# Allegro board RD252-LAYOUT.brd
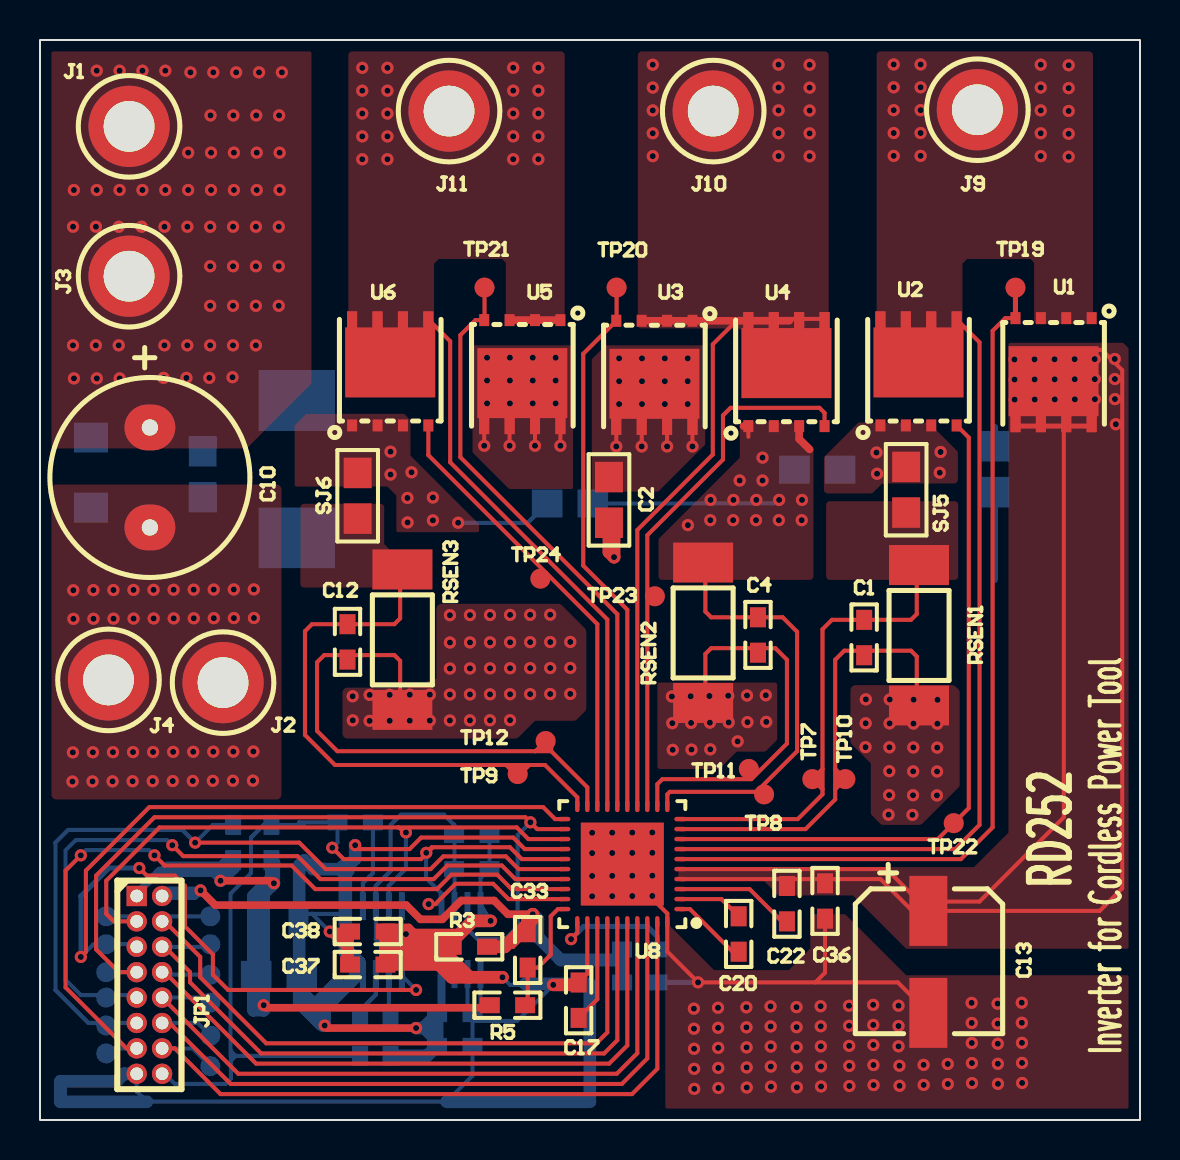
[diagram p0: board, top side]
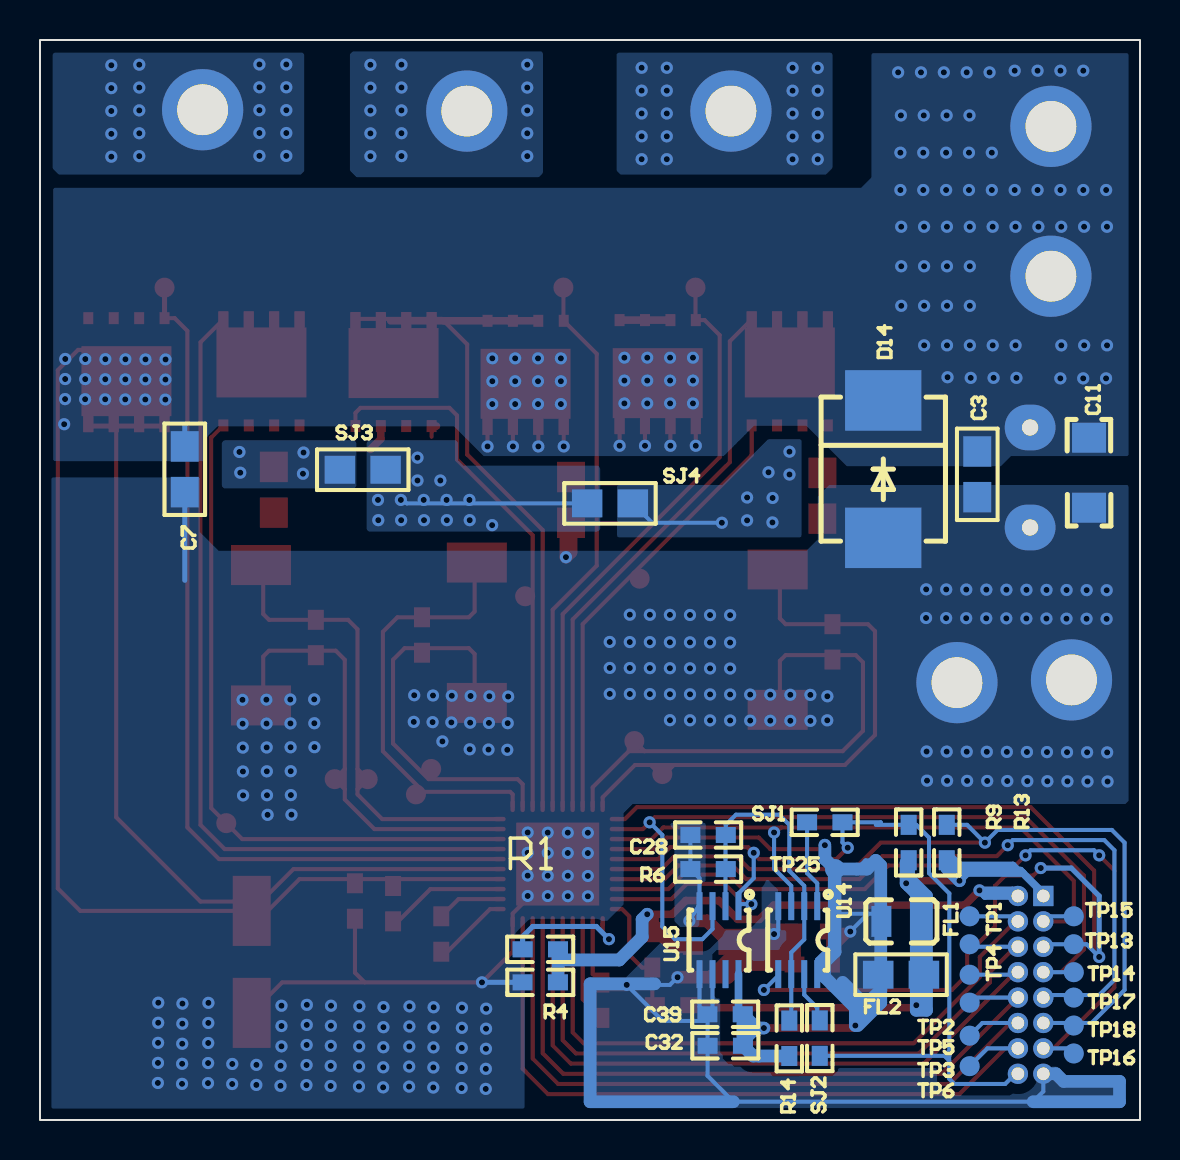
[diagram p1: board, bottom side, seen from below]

Outline 55 x 54 mm; copper layers: TOP, BOTTOM. Coordinates in mm from the lower left corner of the outline.
Outline path: rectangle 0,0 55,54

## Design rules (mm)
constraint set DEFAULT: 

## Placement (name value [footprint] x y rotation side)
C1  -  [0603]  41.21 25.01 270 top
C2  -  [0805]  28.45 32.15 270 top
C3  -  [0805]  8.14 33.43 270 bottom
C4  -  [0603]  35.9 25.14 270 top
C7  -  [0805]  47.76 33.68 270 bottom
C10  -  [CAP_10MM]  5.49 34.63 180 top
C11  -  [0603#3]  2.55 34.12 90 bottom
C12  -  [0603]  15.38 24.79 270 top
C13  -  [CASE_B2]  44.42 10.46 270 top
C17  -  [0603]  26.93 5.11 90 top
C20  -  [0603]  34.93 10.19 270 top
C22  -  [0603]  37.35 9.93 90 top
C28  -  [0603]  20.71 14.25 0 bottom
C32  -  [0603]  19.85 3.71 0 bottom
C33  -  [0603]  24.38 7.62 90 top
C36  -  [0603]  39.25 11.84 270 top
C37  -  [0603]  15.5 7.77 0 top
C38  -  [0603]  15.5 9.42 0 top
C39  -  [0603]  19.86 5.29 0 bottom
D14  -  [DSMC]  12.84 29.11 270 bottom
FL1  -  [L0805]  10.93 9.93 0 bottom
FL2  -  [L0805#2]  13.09 7.26 180 bottom
J1  -  [TP_SM]  4.45 49.68 180 top
J2  -  [TP_SM]  9.15 21.87 180 top
J3  -  [TP_SM]  4.45 42.19 0 top
J4  -  [TP_SM]  3.42 22 0 top
J9  -  [TP_SM]  46.87 50.51 0 top
J10  -  [TP_SM]  33.66 50.45 0 top
J11  -  [TP_SM]  20.45 50.45 0 top
JP1  -  [IDC16_1_27MM]  4.83 11.2 270 top
R1  -  [0603]  30.87 8.53 180 bottom
R3  -  [0603]  20.58 8.66 0 top
R4  -  [0603]  29.1 6.88 0 bottom
R5  -  [0603]  22.49 5.74 0 top
R6  -  [0603]  20.71 12.55 0 bottom
R9  -  [0603]  11.57 14.76 270 bottom
R13  -  [0603]  9.66 14.76 270 bottom
R14  -  [0603]  17.54 3.2 90 bottom
RSEN1  -  [2512]  43.95 20.73 270 top
RSEN2  -  [2512]  33.16 20.85 270 top
RSEN3  -  [2512]  18.12 20.51 270 top
SJ1  -  [0603]  16.65 14.88 180 bottom
SJ2  -  [0603]  16.01 4.98 270 bottom
SJ3  -  [0603#2]  40.01 32.51 180 bottom
SJ4  -  [0603#2]  27.64 30.83 180 bottom
SJ5  -  [0603#2]  43.31 30.37 90 top
SJ6  -  [0603#2]  15.88 30.07 90 top
TP1  -  [TP2]  8.52 10.19 0 bottom
TP2  -  [TP2]  8.52 7.26 0 bottom
TP3  -  [TP2]  8.52 4.22 0 bottom
TP4  -  [TP2]  8.52 8.79 270 bottom
TP5  -  [TP2]  8.52 5.87 270 bottom
TP6  -  [TP2]  8.52 2.69 270 bottom
TP7  -  [TP2]  38.62 17.04 0 top
TP8  -  [TP2]  36.2 16.28 180 top
TP9  -  [TP2]  23.89 17.3 180 top
TP10  -  [TP2]  40.27 17.04 180 top
TP11  -  [TP2]  35.44 17.55 180 top
TP12  -  [TP2]  25.28 18.95 270 top
TP13  -  [TP2]  3.31 8.79 90 bottom
TP14  -  [TP2]  3.31 7.39 90 bottom
TP15  -  [TP2]  3.31 10.19 90 bottom
TP16  -  [TP2]  3.31 3.33 90 bottom
TP17  -  [TP2]  3.31 6.12 90 bottom
TP18  -  [TP2]  3.31 4.72 90 bottom
TP19  -  [TP2]  48.77 41.62 0 top
TP20  -  [TP2]  28.83 41.62 180 top
TP21  -  [TP2]  22.23 41.62 180 top
TP22  -  [TP2]  45.69 14.84 180 top
TP23  -  [TP2]  30.74 26.19 180 top
TP24  -  [TP2]  25.02 27.07 180 top
TP25  -  [TP2]  15.25 12.55 90 bottom
U1  -  [SOP_8T]  52.58 40.09 0 top
U2  -  [SOP_8T]  42.02 34.73 180 top
U3  -  [SOP_8T]  32.62 39.96 0 top
U4  -  [SOP_8T]  35.42 34.7 180 top
U5  -  [SOP_8T]  26.02 40 0 top
U6  -  [SOP_8T]  15.61 34.73 180 top
U8  -  [WQFN_40]  32.02 10.55 180 top
U14  -  [SSOP_8]  16.14 10.69 0 bottom
U15  -  [SSOP_8]  20.07 10.69 0 bottom

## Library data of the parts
C1 C4 C12 = 0.001uF
C2 C3 C7 = 10uF
C10 = 220uF_60V
C11 C32 C36 = 0.1uF: alternate symbols: (1206)
C13 = 20uF_60V
C17 C28 C37 C38 = 1uF
C20 = 47nF/16V
C22 = 1uF/16V
C33 = 100nF
C39 = 4.7uF
D14 = SMCJ22A
FL1 FL2 = BLM21PG221SN1D: alternate symbols: (0805)
J1 J3 = INV
J2 J4 = PGND
J9 = MOTOR_U
J10 = MOTOR_V
J11 = MOTOR_W
JP1 = CONN_16PINJ
R1 = O_OHM
R3 R4 = 0E
R5 R9 R13 = 10K
R6 = 1.5k/0.1%
R14 = 100k/0.1%
RSEN1-RSEN3 = 5mOhm_5W
SJ1-SJ6 = SJ: alternate symbols: (0805)
TP1-TP25 = TPB1_27
U1-U6 = TPH1R204PB: alternate symbols: (SOP_8T_1)
U8 = DRV8323S
U14 U15 = TC75W58FK

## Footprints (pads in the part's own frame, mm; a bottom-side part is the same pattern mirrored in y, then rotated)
0603
  rect 1x0.8 smd: 1(0,0) 2(1.77,0)
0603#2
  rect 1.524x1.397 smd: 1(0,0) 2(2.286,0)
0603#3
  rect 1.5x1.7 smd: 1(0,0) 2(-3.5,0)
0805
  rect 1.524x1.397 smd: 1(0,0) 2(2.286,0)
2512
  rect 2x3 smd: 1(0,0) 2(-7.021,0)
CAP_10MM
  oval 2.54x2.286 hole 0.813: 1(0,0) 2(0,5)
CASE_B2
  rect 3.5x1.9 smd: 1(0,0) 2(5.1,0)
DSMC
  rect 3.03x3.82 smd: A(0,0) C(-6.87,0)
IDC16_1_27MM
  rect 1.016x1.016 hole 0.635: 1(0,0)
  round 1.016 hole 0.635: 2(0,1.27) 3(1.27,0) 4(1.27,1.27) 5(2.54,0) 6(2.54,1.27) 7(3.81,0) 8(3.81,1.27) 9(5.08,0) 10(5.08,1.27) 11(6.35,0) 12(6.35,1.27) 13(7.62,0) 14(7.62,1.27) 15(8.89,0) 16(8.89,1.27)
L0805
  rect 1x1.55 smd: 1(0,0) 2(2,0)
L0805#2
  rect 1.524x1.397 smd: 1(0,0) 2(2.286,0)
SOP_8T
  rect 0.5x0.6 smd: 1(0,0) 2(-1.27,0) 3(-2.54,0) 4(-3.81,0)
  rect 0.5x0.8 smd: 5(-3.81,-5.3) 6(-2.54,-5.3) 7(-1.27,-5.3) 8(0,-5.3)
SSOP_8
  rect 0.3x1.4 smd: 1(0,0) 2(0.65,0) 3(1.3,0) 4(1.95,0) 5(1.95,3.4) 6(1.3,3.4) 7(0.65,3.4) 8(0,3.4)
TP2
  round 1 smd: 1(0,0)
TP_SM
  round 4.064 hole 2.54: 1(0,0)
WQFN_40
  oval 0.6x0.22 smd: 1(0,0) 2(0,-0.5) 3(0,-1) 4(0,-1.5) 5(0,-2) 6(0,-2.5) 7(0,-3) 8(0,-3.5) 9(0,-4) 10(0,-4.5) 21(5.8,-4.5) 22(5.8,-4) 23(5.8,-3.5) 24(5.8,-3) 25(5.8,-2.5) 26(5.8,-2) 27(5.8,-1.5) 28(5.8,-1) 29(5.8,-0.5) 30(5.8,0)
  oval 0.22x0.6 smd: 11(0.65,-5.15) 12(1.15,-5.15) 13(1.65,-5.15) 14(2.15,-5.15) 15(2.65,-5.15) 16(3.15,-5.15) 17(3.65,-5.15) 18(4.15,-5.15) 19(4.65,-5.15) 20(5.15,-5.15) 31(5.15,0.65) 32(4.65,0.65) 33(4.15,0.65) 34(3.65,0.65) 35(3.15,0.65) 36(2.65,0.65) 37(2.15,0.65) 38(1.65,0.65) 39(1.15,0.65) 40(0.65,0.65)
  rect 4.15x4.15 smd: 41(2.9,-2.25)

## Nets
+5V: FL1.1 FL2.2 JP1.1 R5.1 R9.2 R13.2
+5V_A: C32.1 C37.1 C38.1 C39.1 FL1.2 FL2.1 R14.1 TP25.1 U8.24 U14.8 U15.8
AGND: C17.2 C28.2 C32.2 C37.2 C38.2 C39.2 JP1.15 R3.1 R6.2 U8.32 U14.4 U15.4 U15.5 U15.6
GND: C33.2 JP1.2 R1.2 R3.2 R4.1
PGND: C1.2 C2.2 C3.2 C4.2 C7.2 C10.2 C11.2 C12.2 C13.2 C36.2 D14.A J2.1 J4.1 R4.2 RSEN1.1 RSEN2.1 RSEN3.1 TP10.1 TP11.1 TP12.1 U8.9 U8.12 U8.19 U8.40 U8.41
V0: JP1.8 TP2.1 U8.36
AINB10: JP1.3 TP15.1 U8.23 U14.3
AINB11: JP1.7 TP14.1 U8.22 U15.3
AINB12: JP1.5 TP13.1 U8.21 U14.5
EMG: JP1.16 R9.1 SJ1.2 SJ2.2 U8.25 U8.29 U15.1
GHA: TP19.1 U1.4 U8.6
GHB: TP20.1 U3.4 U8.15
GHC: TP21.1 U5.4 U8.16
GLA: TP22.1 U2.4 U8.8
GLB: TP23.1 U4.4 U8.13
GLC: TP24.1 U6.4 U8.18
NETC22_1: C22.1 U8.3
NETR1_1: R1.1 U8.31
NETR5_2: C33.1 R5.2 U8.30
NETR14_2: C28.1 R6.1 R14.2 U14.2 U14.6 U15.2
NETSJ4_2: SJ4.2 SJ6.2 U6.1 U6.2 U6.3
NETU2_1: SJ3.1 SJ5.2 U2.1 U2.2 U2.3
NETU8_1: C20.2 U8.1
NETU8_2: C20.1 U8.2
NETU8_33: C17.1 U8.33
NETU14_1: SJ1.1 U14.1
NETU14_7: SJ2.1 U14.7
SCLK: JP1.13 TP16.1 U8.28
SDI: JP1.9 TP17.1 U8.27
SDO: JP1.11 R13.1 TP18.1 U8.26
SHA: J9.1 U1.1 U1.2 U1.3 U2.5 U2.6 U2.7 U2.8 U8.7
SHB: J10.1 U3.1 U3.2 U3.3 U4.5 U4.6 U4.7 U4.8 U8.14
SHC: J11.1 U5.1 U5.2 U5.3 U6.5 U6.6 U6.7 U6.8 U8.17
SNA: C1.1 RSEN1.2 SJ5.1 TP7.1 U8.10
SNB: C4.1 RSEN2.2 SJ3.2 SJ4.1 TP8.1 U4.1 U4.2 U4.3 U8.11
SNC: C12.1 RSEN3.2 SJ6.1 TP9.1 U8.20
U0: JP1.4 TP1.1 U8.34
VM: C2.1 C3.1 C7.1 C10.1 C11.1 C13.1 C22.2 C36.1 D14.C J1.1 J3.1 U1.5 U1.6 U1.7 U1.8 U3.5 U3.6 U3.7 U3.8 U5.5 U5.6 U5.7 U5.8 U8.4 U8.5
W0: JP1.12 TP3.1 U8.38
X0: JP1.6 TP4.1 U8.35
Y0: JP1.10 TP5.1 U8.37
Z0: JP1.14 TP6.1 U8.39

Pads without a net: U15 7

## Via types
v1: diameter 0.61, hole 0.305, TOP to BOTTOM, 418 vias

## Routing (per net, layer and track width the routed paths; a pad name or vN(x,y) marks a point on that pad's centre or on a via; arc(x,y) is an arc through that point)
+5V: length 51.1
  TOP w0.381: v1(11.19,5.74) 11.31,5.61 22.36,5.61 R5.1 ; v1(11.69,11.84) 11.57,11.96 v1(9.03,11.96)
  BOTTOM w0.203: v1(11.19,5.74) 10.93,5.99 10.93,6.88 ; FL2.2 10.8,10.06
  BOTTOM w0.381: 9.03,12.35 9.14,12.47 ; 9.03,12.35 5.86,12.35 ; 9.03,12.35 v1(9.03,11.96) 8.52,12.47 ; 9.14,12.47 8.52,12.47 ; 9.14,12.47 R13.2 ; JP1.1 4.83,11.33 5.86,12.35 ; 5.86,12.35 5.98,12.47 6.11,12.47 ; 11.19,11.33 10.8,10.95 10.8,10.06 ; 6.11,12.47 6.36,12.72 9.03,12.72 9.41,13.11 ; 6.11,12.47 8.52,12.47 ; 11.57,11.71 11.57,12.09
  BOTTOM w0.635: v1(9.03,11.96) 9.66,12.6 R13.2 ; R9.2 11.69,12.86 v1(11.69,11.84) 11.19,11.33 v1(11.19,5.74) 11.19,5.49 10.68,5.49 10.68,11.2 11.57,12.09 R9.2
+5V_A: length 70.5
  TOP w0.203: U8.24 24.24,13.55 23.66,14.12 19.06,14.12 18.48,13.55 15.95,13.55 v1(15.76,13.74) ; C38.1 15.76,9.42
  TOP w0.381: 14.99,9.42 C38.1 C37.1 ; 14.99,9.42 v1(14.49,9.42) 15.38,8.53 ; 14.99,9.42 15.25,9.17 15.25,7.77 ; v1(14.23,4.72) 14.36,4.6 v1(18.8,4.6)
  BOTTOM w0.203: 13.6,10.31 v1(14.49,9.42) ; 13.6,10.31 12.96,10.31 ; 13.6,10.31 15.5,10.31 ; 13.22,12.98 13.72,12.98 14.16,12.55 ; 19.06,3.2 19.57,3.71 19.85,3.71 19.86,3.72 ; 15.5,10.31 15.5,8.66 16.14,8.03 16.14,7.52 15.77,7.15 ; 15.5,10.31 15.5,12.47 ; 15.15,12.37 15.23,12.55 ; 19.22,4.6 19.86,4.6 ; C39.1 20.07,5.5
  BOTTOM w0.381: 19.34,3.2 19.86,3.72 C39.1 19.17,4.6 ; 19.85,5.11 20.07,5.33 U15.8
  BOTTOM w0.635: 14.23,5.23 14.23,5.61 15.77,7.15 15.77,7.88 15.25,8.41 TP25.1 ; 14.23,5.23 12.96,6.5 ; 14.23,5.23 v1(14.23,4.72) ; v1(15.76,13.74) 15.76,13.05 TP25.1 ; 19.85,3.96 19.22,4.6 19.17,4.6 ; 19.85,3.96 C32.1 19.34,3.2 R14.1 ; 19.85,3.96 19.85,5.28 19.17,4.6 ; 19.17,4.6 v1(18.8,4.6) ; 12.96,6.5 12.96,12.72 13.22,12.98 13.65,12.55 TP25.1 ; 12.96,6.5 12.96,5.87 14.11,4.72 ; 13.98,5.99 14.87,6.88
AGND: length 100.5
  TOP w0.203: U8.32 27.37,7.31 C17.2 ; C38.2 18.17,9.42 v1(18.3,9.3)
  TOP w0.381: 18.69,9.37 20.95,9.37 ; 18.69,9.37 18.44,9.63 17.14,9.63 ; 18.69,9.37 18.95,9.12 19.81,9.12
  TOP w0.635: 20.8,9.12 21.64,9.96 v1(22.53,9.96) ; 20.8,9.12 20.35,8.66 ; 20.8,9.12 19.81,9.12 ; v1(25.66,6.76) 26.81,6.76 ; 17.27,8.26 20.07,8.26 20.45,7.87 ; 17.27,8.26 C37.2 ; 17.27,8.26 C38.2 17.58,9.12 18.95,9.12 ; 17.28,7.78 19.94,7.78 20.58,7.14 21.47,7.14 ; 20.35,8.66 R3.1 ; 20.35,8.66 17.3,8.66 17.65,9.02 20.19,9.02 ; 20.58,8.03 21.47,7.14 ; 21.47,7.14 v1(23.12,7.14)
  BOTTOM w0.203: U15.6 21.38,5.61 ; 21.38,5.61 21.62,5.37 21.62,5.28 ; 21.38,5.61 21.38,5.2 21.62,4.95 ; 21.62,5.28 22.02,5.68 U15.5 ; 21.62,5.28 21.62,4.95 ; v1(18.3,9.3) 18.09,9.51 U14.4 ; v1(22.53,9.96) 22.06,10.72 22.02,10.78 22.02,12.09 R6.2 C28.2 ; 21.62,4.95 23.86,4.95 v1(25.66,6.76) 23.5,6.76 v1(23.12,7.14) ; 21.62,4.95 C32.2 21.62,2.21 20.33,0.91 5.34,0.91 4.83,1.42 JP1.15
  BOTTOM w0.635: 24.26,6.81 27.49,6.81 27.49,0.91 20.33,0.91 ; 5.34,0.91 1.02,0.91 1.02,1.93 3.82,1.93 4.2,2.31 JP1.15
GND: length 35.6
  TOP w0.203: C33.2 23.66,8.66 23.24,8.66
  TOP w0.381: v1(24.64,10.29) 23.39,10.29 22.71,10.97 21.06,10.97 20.12,10.03 19.02,10.03 18.31,10.74 8.76,10.74 v1(8.03,11.48)
  TOP w0.635: R3.2 23.24,8.66 23.97,9.39 ; 23.97,9.39 C33.2 24.38,10.03 v1(24.64,10.29) 24.64,10.06 23.97,9.39
  BOTTOM w0.381: 6.38,11.48 v1(8.03,11.48) 7.75,11.2 JP1.2 6.38,11.48
  BOTTOM w0.635: 29.1,6.89 29.1,8.26 ; 29.1,8.26 28.85,8 26.04,8 24.89,9.14 24.89,10.03 v1(24.64,10.29) ; 29.1,8.26 R1.2
PGND: length 101.8
  TOP w0.203: 35.67,23.59 36.77,23.59 37.35,23.01 37.35,18.82 35.57,17.04 31.12,17.04 30.87,16.79 U8.12 ; 35.67,23.59 C4.2 ; 35.67,23.59 33.56,23.59 33.27,23.3 33.27,20.72 ; 39.76,16.54 TP10.1 39.76,17.55 ; 39.76,16.54 39.76,16.03 38.28,14.55 U8.9 ; 39.76,16.54 39.76,17.55 ; 25.56,18.44 25.56,18.67 TP12.1 24.77,18.44 ; 25.56,18.44 27.37,16.63 U8.19 ; 25.56,18.44 24.77,18.44 ; C36.2 39.25,7.37 38.77,6.88 ; 15.15,23.25 17.72,23.25 18.01,22.96 18.01,21.02 ; 15.15,23.25 C12.2 ; 15.15,23.25 14.21,23.25 13.85,22.89 13.85,19.46 14.87,18.44 24.77,18.44 ; 40.98,23.46 43.55,23.46 43.84,23.18 43.84,21.24 ; 40.98,23.46 40.21,23.46 39.76,23.01 39.76,17.55 ; 40.98,23.46 C1.2 ; 38.77,6.88 v1(32.9,6.88) 31.37,8.42 31.37,10.32 30.74,10.95 ; 38.77,6.88 42.89,6.88 C13.2 ; 27.37,14.6 v1(27.61,14.36) ; v1(30.62,14.38) 30.87,14.63
  TOP w0.635: 28.7,29.61 C2.2 28.45,28.4 v1(28.7,28.14) 28.7,29.61 ; 28.7,29.61 28.7,29.72
  BOTTOM w0.254: R4.2 v1(32.9,6.88) ; 47.76,26.98 C7.2
  vias: v1(1.64,18.38) v1(1.62,16.92) v1(1.67,26.49) v1(1.67,25.06) v1(2.65,18.39) v1(2.63,16.93) v1(2.67,26.49) v1(2.67,25.06) v1(3.65,18.39) v1(3.63,16.93) v1(3.67,26.5) v1(3.68,25.07) v1(4.63,16.94) v1(4.67,26.5) v1(4.68,25.07) v1(4.65,18.4) v1(5.63,16.94) v1(5.68,26.51) v1(5.68,25.08) v1(5.65,18.4) v1(6.64,16.95) v1(6.68,26.51) v1(6.68,25.08) v1(6.66,18.41) v1(7.64,16.95) v1(7.68,26.52) v1(7.69,25.09) v1(7.66,18.41) v1(8.64,16.96) v1(8.69,26.52) v1(8.69,25.09) v1(8.66,18.41) v1(9.65,16.96) v1(9.69,26.53) v1(9.69,25.1) v1(9.67,18.42) v1(10.65,16.97) v1(10.69,26.53) v1(10.7,25.1) v1(10.67,18.42) v1(15.63,21.19) v1(15.64,19.98) v1(16.48,21.26) v1(16.48,19.96) v1(17.49,21.26) v1(17.48,19.96) v1(18.49,21.27) v1(18.49,19.97) v1(19.49,21.27) v1(19.49,19.97) v1(20.5,25.24) v1(20.5,23.87) v1(20.5,22.57) v1(20.49,21.27) v1(20.49,19.98) v1(21.5,25.25) v1(21.5,23.88) v1(21.5,22.58) v1(21.5,21.28) v1(21.5,19.98) v1(22.5,25.25) v1(22.5,23.88) v1(22.5,22.58) v1(22.5,21.28) v1(22.5,19.99) v1(23.5,25.26) v1(23.5,23.89) v1(23.5,22.59) v1(23.5,21.29) v1(23.5,19.99) v1(24.51,25.26) v1(24.51,23.89) v1(24.51,22.59) v1(24.51,21.29) v1(25.51,25.27) v1(25.51,23.9) v1(25.51,22.6) v1(25.51,21.3) v1(26.51,23.9) v1(26.51,22.6) v1(26.51,21.3) v1(27.61,13.35) v1(27.61,12.2) v1(27.61,11.19) v1(28.61,14.37) v1(28.61,13.35) v1(28.61,12.21) v1(28.61,11.19) v1(29.61,14.37) v1(29.61,13.36) v1(29.61,12.21) v1(29.61,11.2) v1(30.62,13.36) v1(30.62,12.22) v1(30.62,11.2) v1(31.59,21.17) v1(31.61,19.84) v1(31.64,18.51) v1(32.53,21.19) v1(32.55,19.85) v1(32.58,18.52) v1(32.69,5.57) v1(32.7,4.56) v1(32.7,3.56) v1(32.71,2.56) v1(32.71,1.56) v1(33.47,21.2) v1(33.49,19.87) v1(33.51,18.53) v1(33.9,5.61) v1(33.91,4.61) v1(33.91,3.61) v1(33.92,2.6) v1(33.92,1.6) v1(34.41,21.21) v1(34.43,19.88) v1(34.88,18.93) v1(35.32,5.64) v1(35.32,4.63) v1(35.33,3.63) v1(35.33,2.63) v1(35.34,1.62) v1(35.35,21.23) v1(35.37,19.89) v1(36.29,21.24) v1(36.31,19.91) v1(36.53,5.68) v1(36.53,4.68) v1(36.54,3.68) v1(36.54,2.67) v1(36.55,1.67) v1(37.83,5.64) v1(37.83,4.64) v1(37.83,3.64) v1(37.84,2.63) v1(37.84,1.63) v1(39.03,5.69) v1(39.04,4.69) v1(39.04,3.68) v1(39.05,2.68) v1(39.05,1.68) v1(40.45,5.71) v1(40.46,4.71) v1(40.46,3.71) v1(40.46,2.7) v1(40.47,1.7) v1(41.29,21.03) v1(41.28,19.84) v1(41.28,18.64) v1(41.66,5.76) v1(41.66,4.75) v1(41.67,3.75) v1(41.67,2.75) v1(41.68,1.75) v1(42.43,15.27) v1(42.49,21.02) v1(42.48,19.83) v1(42.47,18.63) v1(42.46,17.44) v1(42.46,16.25) v1(42.93,5.71) v1(42.93,4.7) v1(42.93,3.68) v1(42.97,2.71) v1(42.98,1.71) v1(43.62,15.26) v1(43.68,21.02) v1(43.67,19.82) v1(43.67,18.63) v1(43.66,17.43) v1(43.65,16.24) v1(44.18,2.76) v1(44.18,1.75) v1(44.85,16.23) v1(44.88,21.01) v1(44.87,19.81) v1(44.86,18.62) v1(44.85,17.43) v1(45.39,2.8) v1(45.39,1.8) v1(46.58,5.86) v1(46.59,4.85) v1(46.59,3.85) v1(46.59,2.85) v1(46.6,1.84) v1(47.88,5.82) v1(47.88,4.82) v1(47.89,3.81) v1(47.89,2.81) v1(47.9,1.81) v1(49.09,5.86) v1(49.09,4.86) v1(49.1,3.86) v1(49.1,2.86) v1(49.11,1.85)
V0: length 34.2
  TOP w0.203: U8.36 29.37,3.73 28.46,2.82 10.8,2.82 6.23,7.39 JP1.8
  BOTTOM w0.203: TP2.1 6.23,7.26 JP1.8
AINB10: length 33.7
  TOP w0.203: JP1.3 3.69,9.93 3.31,10.31 3.31,11.96 5.98,14.63 17.92,14.63 ; 17.92,14.63 23.83,14.63 24.42,14.05 U8.23 ; 17.92,14.63 v1(18.3,14.38)
  BOTTOM w0.203: v1(18.3,14.38) 18.3,12.57 17.44,11.71 U14.3 ; TP15.1 4.58,10.19 JP1.3
AINB11: length 42.2
  TOP w0.203: JP1.7 3.95,7.39 2.8,8.53 2.8,12.22 5.72,15.14 24.27,15.14 v1(24.52,14.88) 24.86,14.55 U8.22
  BOTTOM w0.203: 23.25,9.04 23.89,9.68 23.89,14.25 v1(24.52,14.88) ; 23.25,9.04 21.88,9.04 21.38,9.55 U15.3 ; 23.25,9.04 23.27,9.04 ; TP14.1 JP1.7
AINB12: length 58.8
  TOP w0.203: v1(4.96,12.6) 5.34,12.22 6.74,12.22 7.25,11.71 7.25,9.68 8.64,8.28 8.64,7.26 9.41,6.5 v1(18.8,6.5) ; v1(2.04,8.15) 2.29,8.41 2.29,12.47 5.47,15.65 25.16,15.65 25.76,15.05 U8.21
  BOTTOM w0.203: U14.5 18.09,7.22 v1(18.8,6.5) ; v1(2.04,8.15) 2.68,8.79 TP13.1 4.71,8.79 4.83,8.66
  BOTTOM w0.254: v1(2.04,8.15) 2.04,11.2 3.44,12.6 v1(4.96,12.6)
EMG: length 53.7
  TOP w0.203: v1(19.43,10.79) 19.76,10.79 20.78,11.81 22.66,11.81 23.42,11.05 U8.29 ; v1(19.31,13.36) 19.59,13.64 23.5,13.64 24.09,13.05 U8.25 ; 19.59,13.59 19.05,13.05 15.18,13.05 v1(14.61,13.61)
  BOTTOM w0.203: JP1.16 6.23,2.31 6.74,1.8 9.28,1.8 9.54,2.06 9.54,2.97 ; 9.53,3.45 9.53,11.33 10.55,12.34 10.55,14.12 11.19,14.76 R9.1 13.09,14.76 ; 9.53,3.45 9.53,3.21 ; 9.53,3.45 9.78,3.21 ; 9.78,3.21 9.54,3.21 9.54,2.97 ; 9.78,3.21 SJ2.2 ; 9.78,3.21 9.54,2.97 ; v1(19.31,13.36) 19.31,12.09 20.07,11.33 U15.1 19.97,10.79 v1(19.43,10.79) ; 13.09,14.76 12.96,14.88 SJ1.2 14.88,13.88 v1(14.61,13.61) ; 13.09,14.76 13.21,14.76
GHA: length 44
  TOP w0.203: U8.6 46.05,13.05 47.63,14.63 47.63,39.46 48.27,40.09 U1.4
  TOP w0.254: U1.4 TP19.1
GHB: length 27.5
  TOP w0.203: U8.15 29.37,25.51 27.16,27.72 27.16,38.31 U3.4 ; 28.83,39.98 TP20.1
GHC: length 29.9
  TOP w0.203: 22.23,40.01 TP21.1 ; U5.4 21.77,40 21.02,39.24 21.02,33.14 28.87,25.29 U8.16
GLA: length 34.5
  TOP w0.203: U8.8 44.89,14.05 TP22.1 46.44,15.6 46.44,34.12 U2.4
GLB: length 27.1
  TOP w0.203: U8.13 30.37,29.24 34.15,33.02 34.15,35.23 34.53,35.61 38.97,35.61 39.23,35.36 U4.4
GLC: length 22.5
  TOP w0.203: U6.4 19.42,33.24 25.31,27.35 27.87,24.79 U8.18
NETC22_1: length 6
  TOP w0.203: U8.3 35.48,11.55 37.09,9.93 C22.1
NETR1_1: length 6.4
  TOP w0.203: v1(26.55,9.04) 26.87,9.36 U8.31
  BOTTOM w0.254: R1.1 30.87,9.17 30.36,9.68 27.19,9.68 v1(26.55,9.04)
NETR5_2: length 6.1
  TOP w0.203: U8.30 25.9,10.55 25.54,10.19 25.54,8.26 24.89,7.62 C33.1 24.38,5.87 R5.2
NETR14_2: length 18.1
  BOTTOM w0.203: U15.2 20.73,14.23 C28.1 20.71,14.76 20.2,15.27 18.04,15.27 17.54,14.76 17.54,12.46 16.79,11.71 U14.2 16.79,9.03 17.44,8.38 U14.6 17.44,5.07 R14.2
NETSJ4_2: length 4.9
  BOTTOM w0.203: SJ4.2 24.39,29.86 v1(20.91,29.86)
  vias: v1(17.53,33.42) v1(17.53,32.27) v1(18.37,31.1) v1(18.38,29.88) v1(18.58,32.39) v1(19.65,31.12) v1(19.65,29.98)
NETU2_1:
  vias: v1(41.82,33.37) v1(41.85,32.31) v1(45.03,33.4) v1(44.99,32.36)
NETU8_1: length 3.8
  TOP w0.203: C20.2 34.63,8.41 32.5,10.55 U8.1
NETU8_2: length 3.3
  TOP w0.203: U8.2 34.07,11.05 C20.1
NETU8_33: length 5.2
  TOP w0.203: U8.33 27.87,6.04 C17.1
NETU14_1: length 4.4
  BOTTOM w0.203: U14.1 16.14,11.84 16.65,12.34 SJ1.1
NETU14_7: length 2.6
  BOTTOM w0.203: U14.7 16.79,6.26 16.14,5.61 16.14,5.11 SJ2.1
SCLK: length 39.1
  TOP w0.203: 4.83,3.58 4.33,3.58 1.28,6.63 1.28,12.47 v1(2.04,13.23) ; U8.28 23.58,11.55 22.86,12.27 20.57,12.27 19.85,11.55 13.76,11.55 12.58,12.72 6.23,12.72 v1(5.72,13.23)
  BOTTOM w0.203: v1(5.72,13.23) 5.47,13.49 2.29,13.49 v1(2.04,13.23) ; TP16.1 3.56,3.58 4.83,3.58
SDI: length 37.1
  TOP w0.203: v1(6.61,13.74) 7.16,13.19 12.88,13.19 14.02,12.05 19.68,12.05 20.37,12.73 23.09,12.73 23.77,12.05 U8.27
  BOTTOM w0.203: 3.18,6.25 TP17.1 ; 3.18,6.25 2.04,6.25 1.28,7.01 1.28,13.49 1.79,13.99 6.36,13.99 v1(6.61,13.74) ; 3.18,6.25 4.71,6.25 JP1.9
SDO: length 41.6
  TOP w0.203: U8.26 23.93,12.55 23.29,13.18 20.17,13.18 19.53,12.55 14.29,12.55 12.96,13.87 v1(7.76,13.87)
  BOTTOM w0.203: 3.18,4.85 TP18.1 ; 3.18,4.85 2.42,4.85 0.77,6.5 0.77,13.87 1.41,14.5 7.12,14.5 v1(7.76,13.87) 8.64,14.76 R13.1 ; 3.18,4.85 JP1.11
SHA: length 41.2
  TOP w0.203: U8.7 45.76,13.55 46.98,14.76 46.98,38.89 U2.5
  vias: v1(42.68,52.78) v1(42.68,51.63) v1(42.68,50.49) v1(42.68,49.35) v1(42.68,48.21) v1(44.03,52.78) v1(44.03,51.63) v1(44.03,50.49) v1(44.03,49.35) v1(44.03,48.21) v1(50.04,52.77) v1(50.04,51.62) v1(50.04,50.48) v1(50.04,49.34) v1(50.04,48.19) v1(51.43,52.74) v1(51.43,51.59) v1(51.43,50.45) v1(51.43,49.31) v1(51.43,48.16)
SHB: length 38.1
  TOP w0.203: U8.14 29.87,29.5 33.64,33.28 33.64,38.78 34.91,40.05 39.17,40.05
  TOP w0.381: 37.47,39.96 U3.1 U3.2 U3.3
  vias: v1(30.64,52.76) v1(30.64,51.62) v1(30.64,50.48) v1(30.64,49.34) v1(30.64,48.19) v1(36.93,52.77) v1(36.93,51.62) v1(36.93,50.48) v1(36.93,49.34) v1(36.93,48.2) v1(38.48,52.76) v1(38.48,51.62) v1(38.48,50.47) v1(38.48,49.33) v1(38.48,48.19)
SHC: length 30.6
  TOP w0.203: 19.42,40.03 20.51,38.94 20.51,32.89 28.37,25.03 U8.17
  TOP w0.381: U5.1 U5.2 U5.3
  vias: v1(16.11,52.61) v1(16.11,51.47) v1(16.11,50.32) v1(16.11,49.18) v1(16.11,48.04) v1(17.37,52.61) v1(17.37,51.47) v1(17.37,50.32) v1(17.37,49.18) v1(17.37,48.04) v1(23.66,52.61) v1(23.66,51.47) v1(23.66,50.33) v1(23.66,49.18) v1(23.66,48.04) v1(24.92,52.61) v1(24.92,51.47) v1(24.92,50.33) v1(24.92,49.18) v1(24.92,48.04)
SNA: length 24.8
  TOP w0.203: 39.12,17.55 39.12,24.54 39.6,25.01 C1.1 43.55,25.01 43.84,25.3 43.84,27.63 RSEN1.2 ; 39.12,17.55 39.12,16.54 ; 39.12,17.55 TP7.1 39.12,16.54 ; U8.10 37.89,15.05 39.12,16.28 39.12,16.54
SNB: length 32.8
  TOP w0.203: U8.11 31.37,16.28 31.49,16.41 35.82,16.41 37.85,18.44 37.85,24.41 37.13,25.14 C4.1 33.56,25.14 33.27,25.43 33.27,27.69 33.16,27.8 33.16,27.8 RSEN2.2 ; 35.42,34.16 U4.1
  TOP w0.381: U4.3 37.96,34.05 38.48,33.53 ; 35.18,34.7 U4.1
  BOTTOM w0.203: SJ4.1 36.66,30.83 36.79,30.96
  vias: v1(32.39,29.74) v1(33.53,31) v1(33.51,29.99) v1(34.67,31) v1(34.66,29.99) v1(34.98,31.98) v1(35.81,31) v1(35.8,29.99) v1(36.13,33.12) v1(36.13,31.98) v1(36.94,29.99) v1(36.96,31) v1(38.1,31) v1(38.09,29.99)
SNC: length 29.7
  TOP w0.203: 23.3,17.75 23.89,17.17 24.46,17.75 ; 23.3,17.75 24.46,17.75 ; 23.3,17.75 14.75,17.75 13.25,19.25 13.25,24.44 13.6,24.79 C12.1 17.72,24.79 18.01,25.08 18.01,27.42 RSEN3.2 ; 24.46,17.75 25.25,17.75 26.87,16.13 U8.20
U0: length 33.6
  TOP w0.203: U8.34 28.37,4.38 27.82,3.83 11.31,3.83 8.01,7.14 8.01,8.15 6.23,9.93 JP1.4
  BOTTOM w0.203: JP1.4 6.36,10.19 TP1.1
VM: length 110.6
  TOP w0.203: 28.81,34.92 U3.5 v1(28.81,33.68) ; 37,12.05 42.03,12.05 43.62,10.46 C13.1 ; 37,12.05 C22.2 ; 37,12.05 U8.4 ; C13.1 52.98,10.46 54.11,11.58 54.11,37.49 53.09,38.51 51.32,38.51 ; C13.1 42.33,12.55 U8.5 ; C13.1 44.88,10.92 46.97,10.92 51.19,15.14 51.19,36.35 ; 30.08,34.92 U3.6 v1(30.08,33.68) ; v1(23.48,33.71) U5.6 23.48,34.96 ; v1(22.21,33.71) U5.5 22.21,34.96 ; 31.35,34.92 U3.7 v1(31.35,33.68) ; v1(24.75,33.71) U5.7 24.75,34.96 ; v1(32.62,33.68) U3.8 32.62,34.92 ; v1(26.02,33.71) U5.8 26.02,34.96
  TOP w0.254: 48.9,34.7 52.49,34.7
  BOTTOM w0.254: C7.1 47.76,34.68
  vias: v1(1.65,38.73) v1(1.69,46.5) v1(1.65,44.66) v1(1.7,37.08) v1(2.84,52.47) v1(2.84,46.5) v1(2.8,44.66) v1(2.79,38.73) v1(2.84,37.08) v1(3.94,44.66) v1(3.94,38.73) v1(3.98,52.47) v1(3.98,46.5) v1(3.98,37.08) v1(5.12,52.47) v1(5.12,46.5) v1(5.08,44.66) v1(6.22,44.66) v1(6.22,38.73) v1(6.18,37.11) v1(6.27,52.47) v1(6.27,46.5) v1(7.32,37.11) v1(7.41,48.37) v1(7.41,46.5) v1(7.37,44.66) v1(7.36,38.73) v1(7.52,52.38) v1(8.53,50.23) v1(8.51,44.66) v1(8.51,42.69) v1(8.51,40.71) v1(8.51,38.73) v1(8.46,37.11) v1(8.55,48.37) v1(8.55,46.5) v1(8.66,52.38) v1(9.62,37.14) v1(9.67,50.23) v1(9.69,48.37) v1(9.69,46.5) v1(9.65,44.66) v1(9.65,42.69) v1(9.65,40.71) v1(9.65,38.73) v1(9.81,52.38) v1(10.81,50.23) v1(10.84,48.37) v1(10.84,46.5) v1(10.8,44.66) v1(10.8,42.69) v1(10.79,40.71) v1(10.79,38.73) v1(10.95,52.38) v1(11.94,44.66) v1(11.94,42.69) v1(11.94,40.71) v1(11.95,50.23) v1(11.98,48.37) v1(11.98,46.5) v1(12.09,52.38) v1(22.35,38.12) v1(22.35,36.97) v1(22.35,35.83) v1(23.5,38.12) v1(23.5,36.97) v1(23.5,35.83) v1(24.64,38.12) v1(24.64,36.97) v1(24.64,35.83) v1(25.78,38.12) v1(25.78,36.97) v1(25.78,35.83) v1(28.96,38.08) v1(28.96,36.94) v1(28.96,35.8) v1(30.1,38.08) v1(30.1,36.94) v1(30.1,35.8) v1(31.24,38.08) v1(31.24,36.94) v1(31.24,35.8) v1(32.39,38.08) v1(32.39,36.94) v1(32.39,35.8) v1(48.72,38.03) v1(48.73,37.02) v1(48.73,36.02) v1(49.73,38.03) v1(49.73,37.03) v1(49.74,36.03) v1(50.73,38.04) v1(50.73,37.03) v1(50.74,36.03) v1(51.73,38.04) v1(51.74,37.04) v1(51.74,36.04) v1(52.73,38.05) v1(52.74,37.04) v1(52.74,36.04) v1(53.74,38.05) v1(53.74,37.05) v1(53.75,36.05) v1(53.79,34.79)
W0: length 35.5
  TOP w0.203: JP1.12 6.49,4.85 9.53,1.8 29.09,1.8 30.37,3.08 U8.38
  BOTTOM w0.203: TP3.1 7.88,4.85 JP1.12
X0: length 33.9
  TOP w0.203: U8.35 28.87,3.99 28.2,3.33 11.06,3.33 7.5,6.88 7.5,7.39 6.23,8.66 6.11,8.66
  BOTTOM w0.203: TP4.1 8.39,8.66 6.11,8.66
Y0: length 34.8
  TOP w0.203: U8.37 29.87,3.34 28.84,2.31 9.91,2.31 JP1.10
  BOTTOM w0.203: TP5.1 8.26,6.12 JP1.10
Z0: length 36.3
  TOP w0.203: 6.11,3.58 6.74,3.58 9.03,1.29 29.6,1.29 30.87,2.56 U8.39
  BOTTOM w0.203: 6.11,3.58 7.63,3.58 TP6.1

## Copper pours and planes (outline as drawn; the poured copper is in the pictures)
+5V_A on BOTTOM: 13.09,5.85 13.09,6.5 13.04,6.5 12.98,6.52 12.96,6.58 12.96,12.47 12.98,12.52 13.04,12.55 15.17,12.55 15.23,12.52 15.25,12.47 15.25,8.15 15.63,8.15 15.63,6.88 15.25,6.88 15.25,6.58 15.23,6.52 15.17,6.5 14.47,6.5 14.47,5.85
AGND on BOTTOM: 22.18,9.65 22.12,9.67 22.09,9.71 22.05,9.74 22.03,9.8 22.03,10.57 21.94,10.72 21.93,10.75 21.92,10.78 21.92,11.88 21.9,11.9 21.82,11.9 21.75,11.93 21.72,12 21.72,14.76 21.75,14.83 21.82,14.86 23.38,14.86 23.45,14.83 23.48,14.75 23.47,14.71 23.45,14.68 23.4,14.62 23.34,14.52 23.3,14.4 23.28,14.29 23.28,14.25 23.28,9.97 23.27,9.93 23.25,9.9 23.03,9.68 22.99,9.66 22.96,9.65
AGND on BOTTOM: outline of 141 points within 0.71,0.6 27.81,11.99 ; 1 cut-out
PGND on TOP: 0.83,16.03 0.65,16.1 0.57,16.28 0.57,31.52 0.65,31.7 0.83,31.77 11.82,31.77 12,31.7 12.07,31.52 12.07,16.28 12,16.1 11.82,16.03
PGND on TOP: 42.17,14.76 42.08,14.78 41.99,14.83 41.61,15.21 41.56,15.3 41.54,15.39 41.54,17.83 40.6,18.77 40.54,18.85 40.52,18.95 40.52,21.49 40.6,21.67 40.78,21.74 45.6,21.74 45.7,21.72 45.78,21.67 45.91,21.54 45.96,21.46 45.98,21.36 45.98,16.79 45.96,16.69 45.91,16.61 44.13,14.83 44.05,14.78 43.95,14.76
PGND on TOP: 31,17.55 30.91,17.59 30.87,17.68 30.87,21.74 30.91,21.83 31,21.87 36.74,21.87 36.83,21.83 36.86,21.74 36.86,19.07 36.85,19.02 36.83,18.98 36.3,18.45 36.26,18.43 36.21,18.42 34.84,18.42 34.01,17.59 33.97,17.56 33.92,17.55
PGND on TOP: 15.38,19.07 15.2,19.15 15.12,19.33 15.12,21.36 15.2,21.54 15.38,21.61 18.3,21.61 19.82,22.06 19.82,25.55 19.9,25.73 20.07,25.81 25.92,25.81 26.01,25.79 26.1,25.73 27.24,24.59 27.29,24.51 27.31,24.41 27.31,20.6 27.29,20.5 27.24,20.42 26.86,20.04 26.78,19.98 26.68,19.96 24.75,19.96 23.94,19.15 23.86,19.09 23.76,19.07
PGND on TOP: 31.37,0.57 31.29,0.6 31.26,0.67 31.26,10.32 31.37,10.43 31.47,10.32 31.47,9.73 33.71,7.49 37.43,7.49 38.52,8.58 38.52,10.19 38.55,10.26 38.62,10.29 40.23,10.29 40.26,10.28 40.28,10.26 43.31,7.24 54.35,7.24 54.41,7.22 54.43,7.16 54.43,0.67 54.4,0.6 54.33,0.57
PGND on BOTTOM: 30.87,0.57 30.8,0.6 30.77,0.67 30.77,7.78 30.8,7.85 30.87,7.88 31.59,7.88 31.62,7.92 31.62,9.19 31.34,9.19 31.28,9.21 31.24,9.27 31.22,9.31 31.2,9.36 31.17,9.4 30.53,10.02 30.36,10.06 27.19,10.06 27.06,10.04 26.92,9.96 26.89,9.96 26.68,9.96 26.64,9.96 26.61,9.99 25.85,10.75 25.82,10.78 25.82,10.82 25.82,15.35 25.37,15.8 0.77,15.8 0.73,15.81 0.7,15.83 0.6,15.93 0.58,15.96 0.57,16 0.57,31.65 0.6,31.72 0.67,31.75 15.5,31.75 15.54,31.74 15.58,31.72 16.08,31.21 16.1,31.18 16.11,31.14 16.11,29.03 16.68,28.46 46.07,28.46 47.01,29.4 47.01,32.03 47.04,32.1 47.11,32.13 54.33,32.13 54.4,32.1 54.43,32.03 54.43,0.67 54.4,0.6 54.33,0.57
NETSJ4_2 on TOP: 17.92,29.39 17.84,29.42 17.81,29.49 17.81,31.22 17.37,31.67 12.84,31.67 12.76,31.7 12.73,31.77 12.73,34.7 12.74,34.74 12.76,34.77 13.27,35.28 13.3,35.3 13.34,35.31 18.17,35.31 18.21,35.3 18.24,35.28 18.5,35.02 18.52,34.99 18.53,34.95 18.53,33.21 21.92,29.82 21.95,29.78 21.95,29.74 21.95,29.49 21.92,29.42 21.85,29.39
NETSJ4_2 on BOTTOM: 17.03,29.13 16.96,29.16 16.93,29.23 16.93,33.93 16.96,34.01 17.03,34.04 18.55,34.04 18.59,34.03 18.62,34.01 20.88,31.75 26.04,31.75 26.12,31.72 26.15,31.65 26.15,29.23 26.12,29.16 26.04,29.13
NETU2_1 on TOP: 39.39,31.33 39.25,31.38 39.2,31.52 39.2,33.07 39.21,33.14 39.25,33.2 40.87,34.82 40.94,34.86 41.02,34.88 44.35,34.88 44.42,34.86 44.49,34.82 45.84,33.47 45.88,33.41 45.9,33.33 45.9,32.02 45.84,31.89 45.7,31.83 42.12,31.83 41.67,31.38 41.61,31.34 41.53,31.33
NETU2_1 on BOTTOM: 39.37,31.58 39.24,31.63 39.18,31.77 39.18,33.8 39.24,33.93 39.37,33.99 45.72,33.99 45.85,33.93 45.91,33.8 45.91,31.77 45.85,31.63 45.72,31.58
SHA on TOP (solid shape): 42.27,39.63 43.04,39.63 43.04,40.43 43.54,40.43 43.54,39.63 44.31,39.63 44.31,40.43 44.81,40.43 44.81,39.63 45.58,39.63 45.58,40.43 46.08,40.43 46.08,39.63 46.18,39.63 46.18,36.13 41.68,36.13 41.68,39.63 41.77,39.63 41.77,40.43 42.27,40.43
SHB on TOP (solid shape): 35.67,39.6 36.44,39.6 36.44,40.4 36.94,40.4 36.94,39.6 37.71,39.6 37.71,40.4 38.21,40.4 38.21,39.6 38.98,39.6 38.98,40.4 39.48,40.4 39.48,39.6 39.57,39.6 39.57,36.1 35.07,36.1 35.07,39.6 35.17,39.6 35.17,40.4 35.67,40.4
SHB on TOP: 35.31,36.15 35.17,36.2 35.12,36.34 35.12,39.43 34.97,39.58 30.08,39.58 29.95,39.63 29.89,39.77 29.89,53.23 29.91,53.3 29.95,53.37 30.02,53.41 30.09,53.43 39.24,53.43 39.38,53.37 39.43,53.24 39.43,36.34 39.38,36.2 39.24,36.15
SHB on BOTTOM: 30.11,47.14 30.06,47.15 30.02,47.18 29.89,47.31 29.86,47.35 29.85,47.4 29.85,53.3 29.89,53.39 29.98,53.43 39.32,53.43 39.36,53.42 39.41,53.39 39.5,53.29 39.51,53.24 39.51,47.52 39.5,47.47 39.47,47.43 39.22,47.18 39.17,47.15 39.12,47.14
SHC on TOP (solid shape): 15.86,39.63 16.63,39.63 16.63,40.43 17.13,40.43 17.13,39.63 17.9,39.63 17.9,40.43 18.4,40.43 18.4,39.63 19.17,39.63 19.17,40.43 19.67,40.43 19.67,39.63 19.76,39.63 19.76,36.13 15.26,36.13 15.26,39.63 15.36,39.63 15.36,40.43 15.86,40.43
SHC on BOTTOM: 15.76,47.27 15.71,47.28 15.67,47.31 15.41,47.56 15.39,47.6 15.38,47.65 15.38,53.24 15.41,53.33 15.5,53.37 26.04,53.37 26.13,53.33 26.17,53.24 26.17,47.52 26.16,47.47 26.13,47.43 26.01,47.31 25.97,47.28 25.92,47.27
SNA on TOP: 39.5,27 39.36,27.06 39.31,27.19 39.31,30.75 39.36,30.88 39.5,30.94 45.72,30.94 45.86,30.88 45.91,30.75 45.91,27.19 45.85,27.06 45.72,27
SNB on TOP: 31.12,27 30.98,27.06 30.92,27.19 30.92,28.97 30.94,29.05 30.98,29.11 34.99,33.12 34.99,34.7 35.04,34.83 35.18,34.89 37.96,34.89 38.09,34.83 38.15,34.7 38.15,34.13 38.62,33.66 38.66,33.6 38.67,33.53 38.67,27.19 38.62,27.06 38.48,27
SNC on TOP: 13.21,26.62 13.07,26.68 13.02,26.81 13.02,30.62 13.07,30.76 13.21,30.81 17.02,30.81 17.15,30.76 17.21,30.62 17.21,28.8 17.61,28.4 19.18,28.4 19.25,28.39 19.31,28.34 19.48,28.16 19.49,28.08 19.49,26.81 19.44,26.68 19.3,26.62
VM on TOP (solid shape): 26.37,35.09 26.27,35.09 26.27,34.29 25.77,34.29 25.77,35.09 25,35.09 25,34.29 24.5,34.29 24.5,35.09 23.73,35.09 23.73,34.29 23.23,34.29 23.23,35.09 22.46,35.09 22.46,34.29 21.96,34.29 21.96,35.09 21.87,35.09 21.87,38.59 26.37,38.59
VM on TOP (solid shape): 32.97,35.06 32.88,35.06 32.88,34.26 32.38,34.26 32.38,35.06 31.61,35.06 31.61,34.26 31.11,34.26 31.11,35.06 30.34,35.06 30.34,34.26 29.84,34.26 29.84,35.06 29.07,35.06 29.07,34.26 28.57,34.26 28.57,35.06 28.47,35.06 28.47,38.56 32.97,38.56
VM on TOP (solid shape): 52.93,35.19 52.83,35.19 52.83,34.39 52.33,34.39 52.33,35.19 51.56,35.19 51.56,34.39 51.06,34.39 51.06,35.19 50.29,35.19 50.29,34.39 49.79,34.39 49.79,35.19 49.02,35.19 49.02,34.39 48.52,34.39 48.52,35.19 48.43,35.19 48.43,38.69 52.93,38.69
VM on TOP: 27.7,31.42 27.62,31.45 27.59,31.52 27.59,38 27.6,38.04 27.62,38.07 28.26,38.7 28.29,38.73 28.33,38.73 33.16,38.73 33.23,38.7 33.26,38.63 33.26,33.81 33.25,33.77 33.23,33.73 30.94,31.45 30.91,31.43 30.87,31.42
VM on TOP: 23.5,31.55 23.46,31.55 23.43,31.58 21.65,33.35 21.63,33.39 21.62,33.43 21.62,38.63 21.65,38.7 21.73,38.73 26.55,38.73 26.62,38.7 26.65,38.63 26.65,31.65 26.62,31.58 26.55,31.55
VM on TOP: 0.67,33.58 0.6,33.61 0.57,33.68 0.57,53.33 0.6,53.4 0.67,53.43 13.47,53.43 13.54,53.4 13.57,53.33 13.57,36.85 13.56,36.82 13.54,36.78 10.37,33.61 10.34,33.59 10.3,33.58
VM on TOP: 43.34,8.56 43.31,8.57 43.28,8.58 40.64,11.23 36.97,11.23 36.93,11.23 36.89,11.26 36.21,11.94 32.02,11.94 31.94,11.97 31.91,12.05 31.91,12.55 31.94,12.62 32.02,12.65 46.7,12.65 48.42,14.37 48.42,38.76 48.45,38.83 48.52,38.86 54.11,38.86 54.15,38.85 54.18,38.83 54.42,38.58 54.43,38.54 54.43,8.63 54.41,8.58 54.35,8.56
VM on BOTTOM: 6.99,32.69 6.95,32.7 6.92,32.72 6.44,33.2 0.67,33.2 0.6,33.23 0.57,33.3 0.57,53.24 0.6,53.31 0.67,53.34 13.33,53.34 13.4,53.31 13.43,53.24 13.43,47.13 13.95,46.61 54.24,46.61 54.31,46.58 54.34,46.51 54.34,33.05 54.31,32.97 54.24,32.94 46.74,32.94 46.67,32.97 46.64,33.05 46.64,34.16 46.13,34.68 34.3,34.68 32.85,33.23 32.81,33.21 32.77,33.2 20.86,33.2 20.82,33.21 20.78,33.23 19.3,34.71 16.68,34.71 14.65,32.7 14.61,32.69

Small or netless copper shapes (teardrops, artwork), in the pictures only: 2 on TOP, 2 on BOTTOM

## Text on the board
Ref Des/Silkscreen Top: Inverter for Cordless Power Tool | RD252
